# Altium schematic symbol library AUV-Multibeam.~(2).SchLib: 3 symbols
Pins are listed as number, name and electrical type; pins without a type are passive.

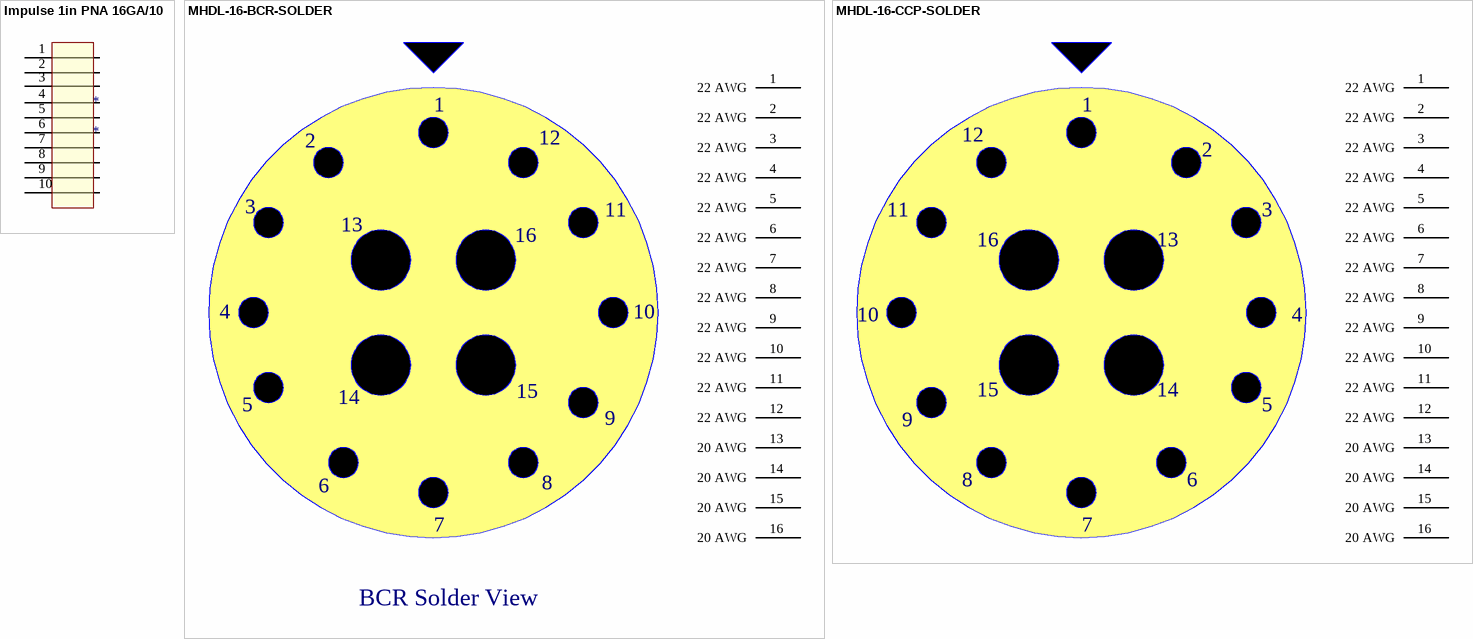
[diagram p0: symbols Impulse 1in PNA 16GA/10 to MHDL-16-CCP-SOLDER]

## Impulse 1in PNA 16GA/10
designator *
pins: 1 17, 2 18, 3 19, 4 20, 5 21, 6 22, 7 23, 8 24, 9 25, 10

## MHDL-16-BCR-SOLDER
designator J?
Impulse MHDL 16 BCR
pins: 1 22 AWG, 2 22 AWG, 3 22 AWG, 4 22 AWG, 5 22 AWG, 6 22 AWG, 7 22 AWG, 8 22 AWG, 9 22 AWG, 10 22 AWG, 11 22 AWG, 12 22 AWG, 13 20 AWG, 14 20 AWG, 15 20 AWG, 16 20 AWG

## MHDL-16-CCP-SOLDER
designator J?
Impulse MHDL 16 CCP
pins: 1 22 AWG, 2 22 AWG, 3 22 AWG, 4 22 AWG, 5 22 AWG, 6 22 AWG, 7 22 AWG, 8 22 AWG, 9 22 AWG, 10 22 AWG, 11 22 AWG, 12 22 AWG, 13 20 AWG, 14 20 AWG, 15 20 AWG, 16 20 AWG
